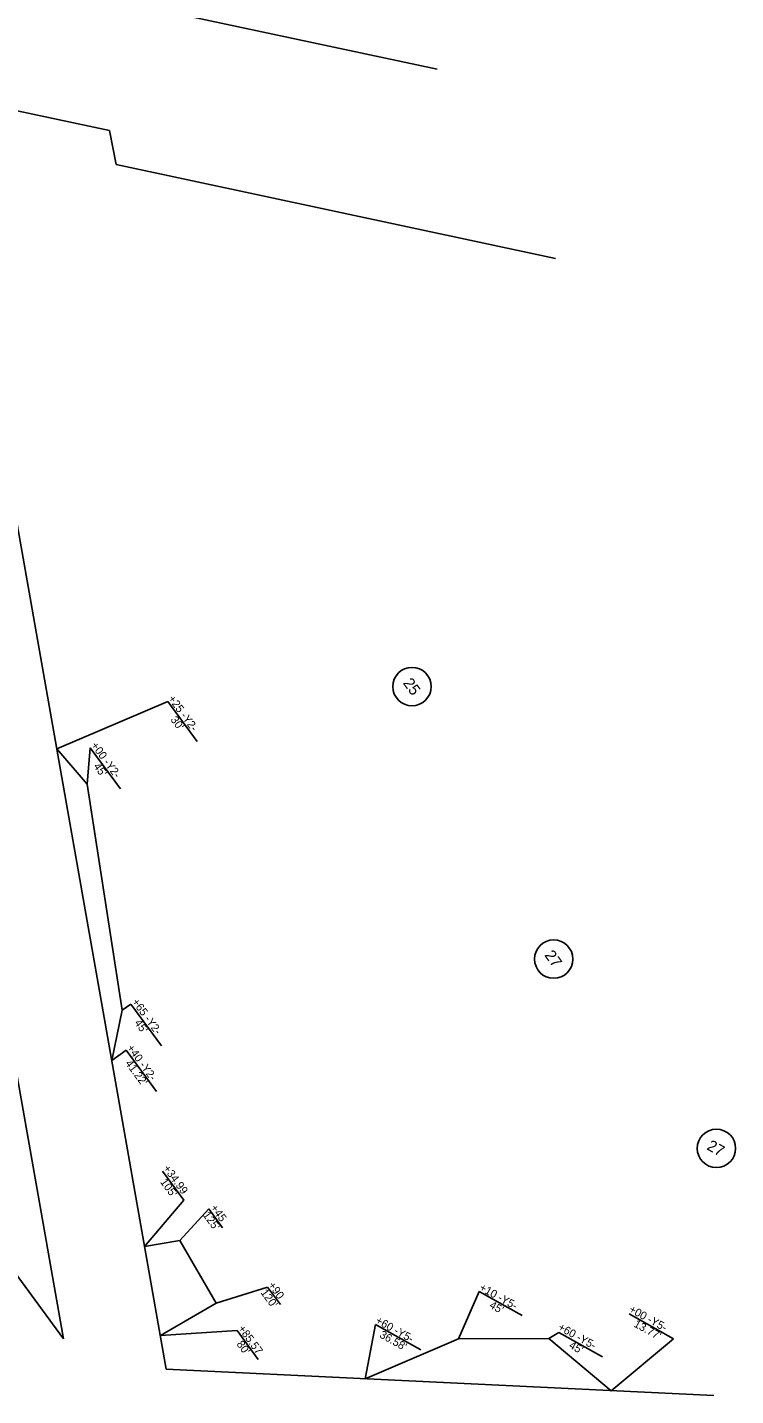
# Model space of a CAD drawing. Extents: x 1762160 to 1765875, y 710174 to 712931.
# Drawn here: x 1763955 to 1764398, y 711557 to 712412 of the extents above; entities that cross this region are included whole.
import ezdxf

# ---------------------------------------------------------------- set-up
doc = ezdxf.new("R2010")
doc.units = 0
for name, color, linetype in [('Exist Other Culture Located Object CELL', 7, 'Continuous'), ('Exist Roads EOP Other', 7, 'Continuous'), ('Exist Utilities Other Pole With Base CELL', 7, 'Continuous'), ('Exist Vegetation Tree CELL', 7, 'Continuous'), ('Exist Vegetation Woods Line', 7, 'Continuous')]:
    doc.layers.add(name, color=color, linetype=linetype)

msp = doc.modelspace()

# ---------------------------------------------------------------- linework, layer by layer
at = {"layer": 'Exist Other Culture Located Object CELL'}
for p, q in [((1764042.81, 711991), (1763973.41, 711961.32)), ((1764042.81, 711991), (1764061.16, 711966.03)), ((1763994.35, 711962.06), (1763992.53, 711939.31)), ((1763994.35, 711962.06), (1764013.26, 711936.31)), ((1764019.81, 711801.7), (1764014.27, 711798.1)), ((1764019.81, 711801.7), (1764038.9, 711775.73)), ((1764016.89, 711772.95), (1764007.82, 711766.57)), ((1764016.89, 711772.95), (1764035.78, 711747.24)), ((1764039.58, 711697.43), (1764052.95, 711679.24)), ((1764052.95, 711679.24), (1764028.36, 711650.33)), ((1764068.37, 711673.95), (1764050.4, 711654.12)), ((1764068.37, 711673.95), (1764077.09, 711662.08)), ((1764105.18, 711624.93), (1764073.02, 711614.9)), ((1764105.18, 711624.93), (1764113.2, 711614.01)), ((1764237.47, 711622.19), (1764224.56, 711592.6)), ((1764237.47, 711622.19), (1764264.34, 711607.23)), ((1764331.18, 711608.2), (1764358.97, 711592.72)), ((1764086.08, 711597.76), (1764038.17, 711594.78)), ((1764086.08, 711597.76), (1764099.35, 711579.7)), ((1764172.56, 711601.54), (1764166.14, 711567.67)), ((1764172.56, 711601.54), (1764200.95, 711585.73)), ((1764287.16, 711596.64), (1764280.9, 711592.78)), ((1764287.16, 711596.64), (1764314.49, 711581.42)), ((1764358.97, 711592.72), (1764319.86, 711560.26))]:
    msp.add_line(p, q, dxfattribs=at)
at = {"layer": 'Exist Roads EOP Other'}
for p, q in [((1763973.41, 711961.32), (1763992.53, 711939.31)), ((1763992.53, 711939.31), (1764014.27, 711798.1)), ((1764014.27, 711798.1), (1764007.82, 711766.57)), ((1764028.36, 711650.33), (1764050.4, 711654.12)), ((1764050.4, 711654.12), (1764073.02, 711614.9)), ((1764038.17, 711594.78), (1764073.02, 711614.9)), ((1764166.14, 711567.67), (1764224.56, 711592.6)), ((1764224.56, 711592.6), (1764280.9, 711592.78)), ((1764280.9, 711592.78), (1764319.86, 711560.26))]:
    msp.add_line(p, q, dxfattribs=at)
at = {"layer": 'Exist Utilities Other Pole With Base CELL'}
for p, q in [((1763893.25, 712453.96), (1764211.09, 712386.16)), ((1763977.6, 711592.75), (1763350.79, 712445.09)), ((1763839.56, 712374), (1763977.6, 711592.75)), ((1763901.16, 712370.18), (1764041.9, 711573.67)), ((1763901.16, 712370.18), (1764006.49, 712347.86)), ((1764006.49, 712347.86), (1764010.48, 712326.46)), ((1764010.48, 712326.46), (1764285.15, 712267.71)), ((1764041.9, 711573.67), (1764384.11, 711557.16))]:
    msp.add_line(p, q, dxfattribs=at)
at = {"layer": 'Exist Vegetation Tree CELL'}
for centre in [(1764195.44, 712000.29), (1764284.03, 711829.96), (1764385.73, 711711.68)]:
    msp.add_circle(centre, 12, dxfattribs=at)

# ---------------------------------------------------------------- texts
at = {"layer": 'Exist Other Culture Located Object CELL'}
for s, rotation, p in [('+25 -Y2-', 306.30835, (1764042.73, 711992.64)), ("30'", 306.30835, (1764044.27, 711979.56)), ('+00 -Y2-', 306.30835, (1763994.56, 711963.47)), ("45'", 306.30835, (1763996.1, 711950.4)), ('+65 -Y2-', 306.30835, (1764020.12, 711803.14)), ("45'", 306.30835, (1764021.66, 711790.07)), ('+40 -Y2-', 306.30835, (1764016.99, 711774.37)), ("41.22'", 306.30835, (1764015.96, 711764.79)), ('+34.99', 306.30835, (1764039.62, 711699.12)), ("105'", 306.30835, (1764037.82, 711690.6)), ("125'", 306.30835, (1764064.47, 711669.96)), ('+45', 306.30835, (1764069.23, 711674.46)), ("120'", 306.30835, (1764100.57, 711621.5)), ('+90', 306.30835, (1764105.27, 711626.08)), ('+10 -Y5-', 330.88857, (1764237.06, 711623.28)), ("45'", 330.88857, (1764243.38, 711612.32)), ('+00 -Y5-', 330.88857, (1764330.59, 711609.68)), ('+60 -Y5-', 330.88857, (1764172.2, 711602.68)), ("13.77'", 330.88857, (1764333.64, 711600.55)), ('+85.57', 306.30835, (1764086.41, 711599.03)), ("36.58'", 330.88857, (1764174.72, 711593.83)), ('+60 -Y5-', 330.88857, (1764286.26, 711598.49)), ("80'", 306.30835, (1764085.52, 711589.27)), ("45'", 330.88857, (1764293.11, 711587.24))]:
    msp.add_text(s, height=5, rotation=rotation, dxfattribs=at).set_placement(p)
at = {"layer": 'Exist Vegetation Woods Line'}
for s, rotation, p in [('25', 306.30835, (1764189.52, 712002.46)), ('27', 306.30835, (1764277.94, 711832.37)), ('27', 330.88857, (1764379.17, 711711.3))]:
    msp.add_text(s, height=7, rotation=rotation, dxfattribs=at).set_placement(p)

doc.saveas('drawing.dxf')
